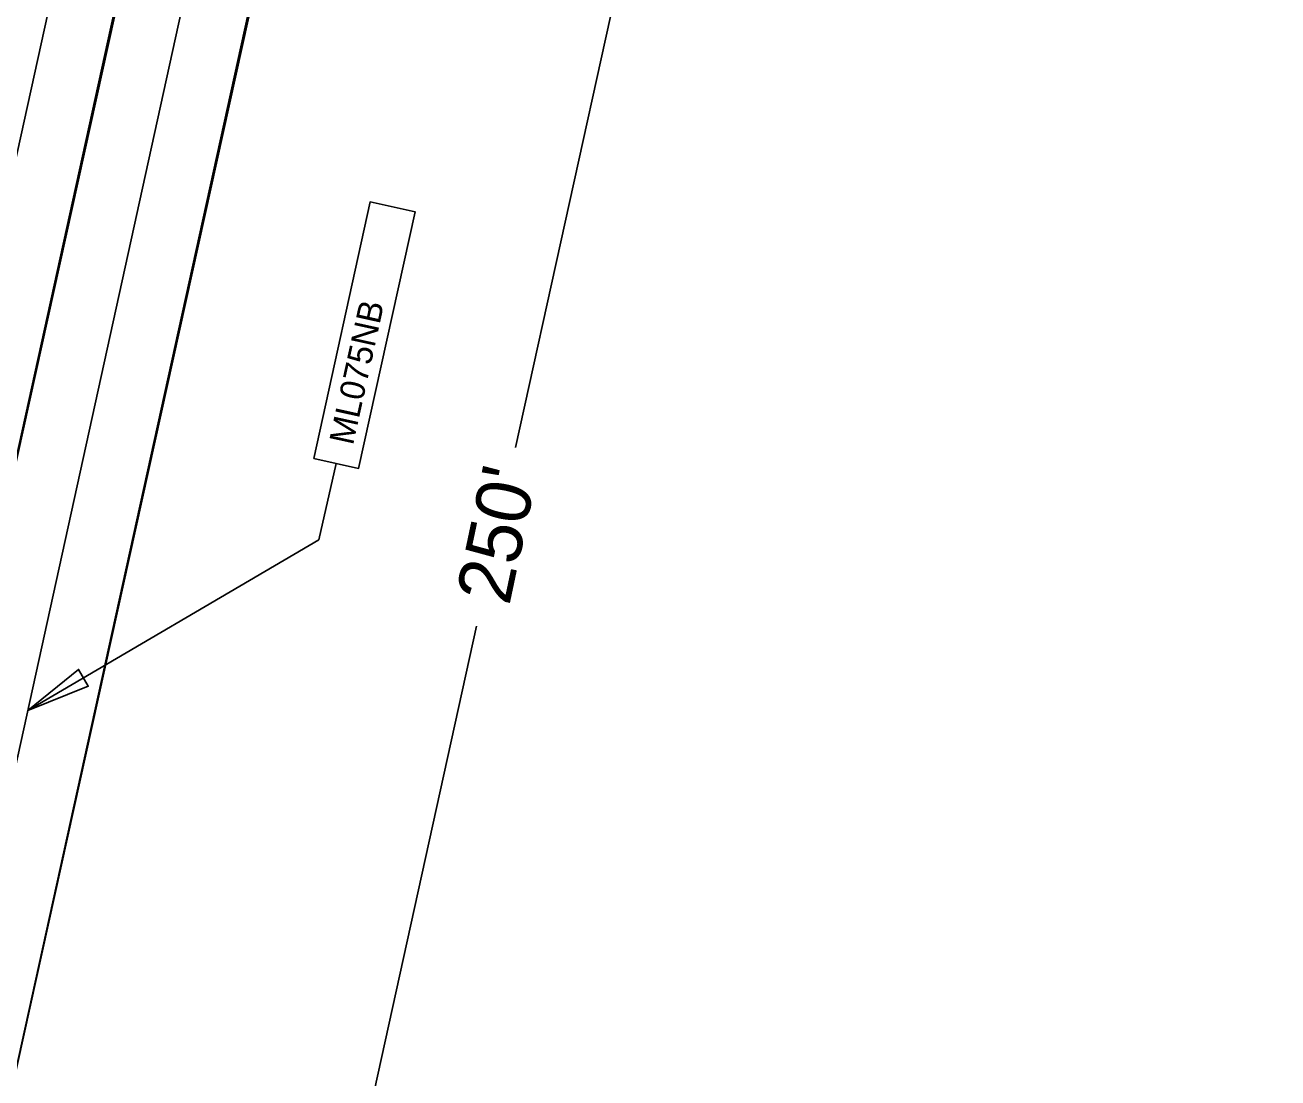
# Model space of a CAD drawing. Extents: x 14104283 to 14120882, y 8635219 to 8671666.
# Drawn here: x 14107599.3 to 14107828.5, y 8638000.8 to 8638193.6 of the extents above; entities that cross this region are included whole.
import ezdxf

# ---------------------------------------------------------------- set-up
doc = ezdxf.new("R2010")
doc.units = 0
for name, color, linetype in [('Default', 7, 'Continuous'), ('dsnPaintExistingBrokenLaneLineWhite', 7, 'Continuous'), ('dsnPaintExistingDoubleCenterYellow', 7, 'Continuous'), ('dsnPaintExistingEdgeLineRightWhite', 7, 'Continuous'), ('dsnStdLabel', 7, 'Continuous'), ('Text', 7, 'Continuous')]:
    doc.layers.add(name, color=color, linetype=linetype)

msp = doc.modelspace()

# ---------------------------------------------------------------- linework, layer by layer
at = {"layer": 'Default'}
for points in [[(14107392.92, 8637186.73), (14107369.48, 8637191.91), (14107655.09, 8638485.14), (14107678.52, 8638479.96)], [(14107602.34, 8638246.31), (14107649.23, 8638236.01), (14107496.22, 8637543.21), (14107449.34, 8637553.51)], [(14107416.35, 8637181.55), (14107649.12, 8638235.55), (14107625.69, 8638240.73), (14107392.92, 8637186.73)]]:
    msp.add_lwpolyline(points, close=True, dxfattribs=at)
at = {"layer": 'dsnPaintExistingBrokenLaneLineWhite'}
for p, q in [((14107381.2, 8637189.32), (14107721.79, 8638731.54)), ((14107447.5, 8637375.04), (14107637.12, 8638238.2))]:
    msp.add_line(p, q, dxfattribs=at)
at = {"layer": 'dsnPaintExistingDoubleCenterYellow'}
msp.add_line((14107435.78, 8637377.61), (14107677.97, 8638480.08), dxfattribs=at)
at = {"layer": 'dsnPaintExistingEdgeLineRightWhite'}
msp.add_line((14107468.79, 8637415.99), (14107828.52, 8639053.57), dxfattribs=at)
at = {"layer": 'dsnStdLabel'}
for p, q in [((14107689.02, 8638116.2), (14107712.3, 8638222.15)), ((14107658.66, 8637977.98), (14107681.84, 8638083.5))]:
    msp.add_line(p, q, dxfattribs=at)
at = {"layer": 'Text'}
for points in [[(14107652.09, 8638114.19), (14107662.41, 8638161.18), (14107670.62, 8638159.38), (14107660.3, 8638112.39)], [(14107652.09, 8638114.19), (14107662.41, 8638161.18), (14107670.62, 8638159.38), (14107660.3, 8638112.39)], [(14107599.75, 8638068.08), (14107609.04, 8638075.59), (14107610.83, 8638072.53)]]:
    msp.add_lwpolyline(points, close=True, dxfattribs=at)
msp.add_lwpolyline([(14107656.19, 8638113.29), (14107653.04, 8638099.34), (14107599.75, 8638068.08)], dxfattribs=at)

# ---------------------------------------------------------------- texts
at = {"layer": 'dsnStdLabel'}
msp.add_text("250'", height=10, rotation=78.0531, dxfattribs=at).set_placement((14107687.85, 8638087.11))
at = {"layer": 'Text'}
msp.add_text('ML075NB', height=4.484, rotation=77.6078, dxfattribs=at).set_placement((14107659.26, 8638116.5))

doc.saveas('drawing.dxf')
